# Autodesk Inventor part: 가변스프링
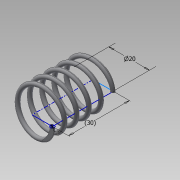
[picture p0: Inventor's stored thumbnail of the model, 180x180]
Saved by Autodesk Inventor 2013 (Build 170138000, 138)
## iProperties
Created: 2019-01
Part Number: 가변스프링
Material: 일반
Document SubType Name: Modeling
Designer: Administrator
Density: 1 g/cm^3
Author: Administrator
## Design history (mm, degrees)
sketch "스케치1"
  geometry: L1 (0, 0)-(10, 0); L2 (10, 0)-(10, 30); L3 (10, 30)-(0, 30); L4 (0, 30)-(0, 0); C1 r 1 at (10, 0)
  constraints: 8 end point, 2 parallel, 1 centre point, 1 coincident, 1 horizontal, 1 perpendicular
  dimensions: "d0" = 20 diameter of L2 L4; "d3" = 2 diameter of C1; "d4" = 30 distance between parallel lines of L1 L3 (derived)
feature "코일1" sketch "스케치1" pitch "d5" = 10; turns "d7" = 5; dims "d6" = 30 (= d4), "d8" = 0, angle "d9" = 90 deg, angle "d10" = 90 deg, "d11" = 0, "d12" = 0
sketch "스케치2"
  geometry: L1 (30, 12.5)-(0, 12.5); L2 (0, 12.5)-(0, -12.5); L3 (0, -12.5)-(30, -12.5); L4 (30, -12.5)-(30, 12.5); 2 further points
  constraints: 8 end point, 2 parallel, 1 coincident, 1 horizontal, 1 midpoint, 1 perpendicular
  dimensions: "d13" = 25 distance between parallel lines of L3 L1; "d15" = 30 distance between parallel lines of L2 L4 (derived)
extrude "돌출1" sketch "스케치2" stored distance "d16" = 25; taper "d17" = 0 deg
node "솔리드1"
